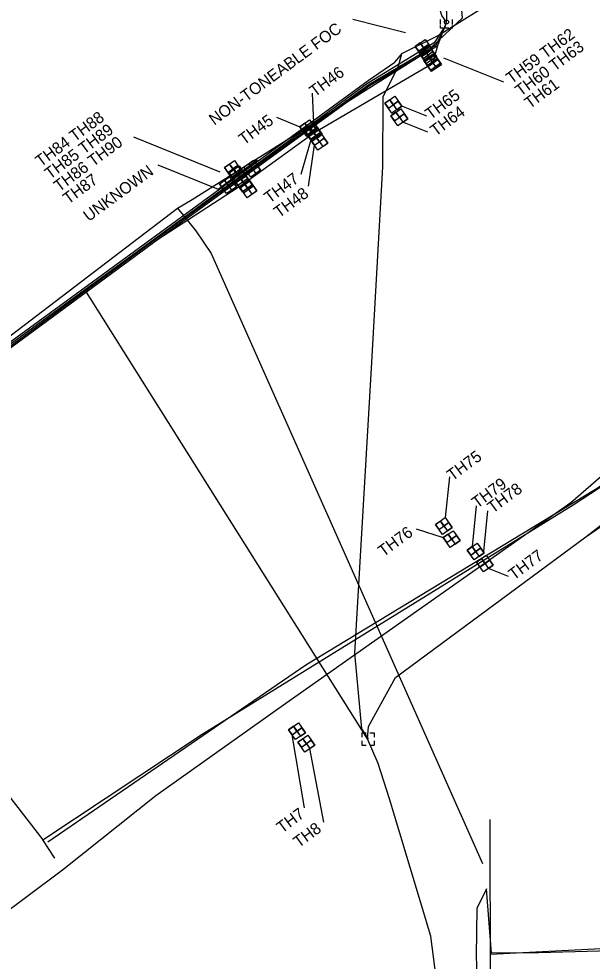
# Model space of a CAD drawing. Extents: x 507915 to 518914, y 880723 to 883087.
# Drawn here: x 509058.8 to 509177.3, y 882135.7 to 882330.6 of the extents above; entities that cross this region are included whole.
import ezdxf

# ---------------------------------------------------------------- set-up
doc = ezdxf.new("R2010")
doc.units = 0
for name, color, linetype in [('CGBack_ep', 7, 'Continuous'), ('CGFace_ep', 7, 'Continuous'), ('ConduitOT', 7, 'Continuous'), ('ConstLines', 7, 'Continuous'), ('Driveway_ep', 7, 'Continuous'), ('GuardrailLt_ep', 7, 'Continuous'), ('GuardrailRt_ep', 7, 'Continuous'), ('Miscellaneous2', 7, 'Continuous'), ('Miscellaneous3', 7, 'Continuous'), ('Miscellaneous4', 7, 'Continuous'), ('PavtAsphalt_ep', 7, 'Continuous'), ('PMBikeLane_ep', 7, 'Continuous'), ('PoleLight_ep', 7, 'Continuous')]:
    doc.layers.add(name, color=color, linetype=linetype)

msp = doc.modelspace()

# ---------------------------------------------------------------- linework, layer by layer
at = {"layer": 'CGBack_ep'}
msp.add_line((509100, 882295.41), (509108.02, 882301.47), dxfattribs=at)
at = {"layer": 'CGFace_ep'}
msp.add_line((509130.88, 882181.71), (509072.38, 882274.63), dxfattribs=at)
at = {"layer": 'ConduitOT'}
for p, q in [((509156.37, 882022.97), (509156.27, 882165.04)), ((509156.29, 882137.16), (509205.32, 882139.66))]:
    msp.add_line(p, q, dxfattribs=at)
at = {"layer": 'ConstLines'}
for points in [[(509091.54, 882291.51), (509094.58, 882293.28), (509143.11, 882323.78), (509150.52, 882330.83), (509150.2, 882334.84), (509149.51, 882377.66), (509149.68, 882420.56), (509148.41, 882517.05)], [(508881.68, 882117.95), (508987.36, 882213.45), (509037.07, 882249.99), (509091.54, 882291.51), (509095.39, 882286.81), (509098.53, 882282.11), (509154.64, 882155.93)], [(509199.56, 882066.8), (509200.82, 882115.11), (509201.3, 882138.4), (509166.31, 882137.42), (509156.53, 882137.36), (509155.46, 882150.65), (509153.51, 882146.59), (509153.35, 882136.84), (509153.6, 882128.58), (509150.89, 882127.59), (509149.73, 882127.8), (509148.69, 882127.65), (509147.06, 882127.81)]]:
    msp.add_lwpolyline(points, dxfattribs=at)
at = {"layer": 'Driveway_ep'}
msp.add_lwpolyline([(509470.15, 882412.29), (509450.24, 882402.26), (509403.86, 882379.8), (509373.73, 882360.54), (509360.26, 882353.19), (509318.09, 882328.86), (509274.11, 882302.04), (509240.02, 882280.9), (509217.6, 882265.28), (509213.42, 882264.48), (509212.3, 882264.04), (509210.28, 882262.92), (509172.92, 882230.49), (509113.97, 882188.99), (509087.11, 882169.95), (509067.76, 882154.57), (509006.28, 882108.6)], dxfattribs=at)
at = {"layer": 'GuardrailRt_ep'}
for p, q in [((509127.86, 882330.55), (509138.7, 882327.79)), ((509159.07, 882317.52), (509146.69, 882322.53)), ((509119.44, 882315.24), (509119.68, 882309.15)), ((509143.12, 882310.48), (509137.95, 882312.57)), ((509112.03, 882310.27), (509116.86, 882308.32)), ((509143.36, 882307.17), (509138.19, 882309.26)), ((509082.49, 882306.2), (509100.36, 882298.97)), ((509117.14, 882298.53), (509119.23, 882305.66)), ((509118.67, 882296.04), (509119.9, 882304.51)), ((509087.53, 882300.46), (509100, 882295.41)), ((509147.82, 882235.9), (509146.97, 882227.47)), ((509153.36, 882229.9), (509152.52, 882221.48)), ((509155.7, 882228.87), (509154.85, 882220.44)), ((509140.91, 882225.15), (509146.54, 882223.32)), ((509160.04, 882215.32), (509155.87, 882216.94)), ((509117.83, 882167.41), (509115.26, 882182.56)), ((509121.85, 882164.48), (509118.95, 882179.68))]:
    msp.add_line(p, q, dxfattribs=at)
at = {"layer": 'Miscellaneous2'}
for p, q in [((509145.96, 882329.48), (509145.96, 882330.48)), ((509147.21, 882329.98), (509147.21, 882329.98)), ((509148.46, 882329.48), (509148.46, 882330.48)), ((509145.96, 882328.73), (509145.96, 882329.23)), ((509146.46, 882328.73), (509145.96, 882328.73)), ((509147.71, 882328.73), (509146.71, 882328.73)), ((509148.46, 882328.73), (509147.96, 882328.73)), ((509148.46, 882328.73), (509148.46, 882329.23))]:
    msp.add_line(p, q, dxfattribs=at)
msp.add_circle((509147.21, 882329.98), 0.438, dxfattribs=at)
at = {"layer": 'Miscellaneous3'}
for points in [[(508882.11, 882139.28), (508990.02, 882214.29), (509029.72, 882243.96), (509087.02, 882285.78), (509130.99, 882317.86), (509136.55, 882321.71), (509138.14, 882323.57), (509145.35, 882327.1), (509198.61, 882360.32), (509243.19, 882384.95), (509308.25, 882420.73), (509348.67, 882443.03), (509435.21, 882484.91)], [(509130.88, 882181.71), (509131.05, 882184.29), (509136.67, 882194.39), (509176.07, 882223.49), (509242.19, 882269.15), (509301.71, 882304.81), (509379.73, 882350.73), (509420.13, 882372.96), (509456.8, 882391.95), (509476.67, 882399.78)], [(509130.88, 882181.71), (509131.05, 882184.29), (509136.67, 882194.39), (509176.07, 882223.49), (509204.83, 882245.76), (509242.19, 882269.15), (509301.71, 882304.81), (509379.73, 882350.73), (509420.13, 882372.96), (509456.8, 882391.95), (509476.67, 882399.78)], [(509137.94, 882323.42), (509137.22, 882320.77), (509134.02, 882314.51), (509133.96, 882300.01), (509131.64, 882258.39), (509128.15, 882199.4), (509129.61, 882183.81), (509130.98, 882181.68)], [(509152.04, 882062.9), (509150.55, 882090.16), (509143.99, 882140.92), (509135.39, 882169.31), (509133.07, 882176.58), (509130.88, 882181.71)]]:
    msp.add_lwpolyline(points, dxfattribs=at)
at = {"layer": 'Miscellaneous4'}
for p, q in [((509129.73, 882182.93), (509129.73, 882182.06)), ((509129.73, 882182.93), (509130.61, 882182.93)), ((509130.98, 882181.68), (509130.98, 882181.68)), ((509131.36, 882182.93), (509132.23, 882182.93)), ((509132.23, 882182.93), (509132.23, 882182.06)), ((509129.73, 882181.31), (509129.73, 882180.43)), ((509129.73, 882180.43), (509130.61, 882180.43)), ((509131.36, 882180.43), (509132.23, 882180.43)), ((509132.23, 882181.31), (509132.23, 882180.43))]:
    msp.add_line(p, q, dxfattribs=at)
at = {"layer": 'PavtAsphalt_ep'}
for points in [[(508946.27, 882182.61), (508990.71, 882213.97), (509030.15, 882243.24), (509087.3, 882285.27), (509131.16, 882317.05), (509145.15, 882325.32), (509146.91, 882329.08), (509147.21, 882329.98), (509147.25, 882330.89), (509146.76, 882351.04), (509146.84, 882378.71), (509146.15, 882394.1), (509143.64, 882423.51), (509144.5, 882493.5)], [(508946.38, 882183.08), (508990.55, 882214.25), (509029.91, 882243.66), (509087.28, 882285.5), (509130.89, 882317.31), (509144.84, 882325.87), (509146.91, 882329.08), (509147.21, 882329.98), (509146.27, 882331.32), (509140.54, 882349.76), (509141.42, 882378.79), (509141.44, 882421.55), (509136.29, 882492.59)], [(508884.81, 882150), (508991.11, 882213.84), (509030.43, 882243.07), (509087.63, 882285.11), (509131.44, 882316.89), (509145.44, 882325.15), (509147.21, 882329.98)], [(508946.67, 882182.29), (508991.11, 882213.84), (509030.43, 882243.07), (509087.63, 882285.11), (509105.29, 882296.6), (509119.78, 882307.05), (509144.41, 882321.5), (509145.44, 882325.15), (509147.21, 882329.98)], [(509064.73, 882160.38), (509118.15, 882196.99), (509178.01, 882233.34), (509198.91, 882246.9), (509212.24, 882254.11), (509211.47, 882255.05), (509211.94, 882257.47), (509212.92, 882261.94), (509216.93, 882269.31), (509226.27, 882274.92), (509234.36, 882278.84), (509241.09, 882279.12), (509244.59, 882279.94)]]:
    msp.add_lwpolyline(points, dxfattribs=at)
at = {"layer": 'PMBikeLane_ep'}
for p, q in [((509140.74, 882324.94), (509142.78, 882326.38)), ((509142.78, 882326.38), (509144.22, 882324.34)), ((509141.76, 882325.66), (509140.74, 882324.94)), ((509142.18, 882322.9), (509140.74, 882324.94)), ((509140.74, 882324.94), (509141.46, 882323.92)), ((509141.4, 882323.85), (509143.44, 882325.29)), ((509142.42, 882324.57), (509141.4, 882323.85)), ((509142.84, 882321.8), (509141.4, 882323.85)), ((509141.4, 882323.85), (509142.12, 882322.82)), ((509141.46, 882323.92), (509143.5, 882325.36)), ((509141.46, 882323.92), (509142.48, 882324.64)), ((509141.65, 882323.45), (509143.69, 882324.89)), ((509142.67, 882324.17), (509141.65, 882323.45)), ((509141.76, 882325.66), (509143.2, 882323.62)), ((509142.48, 882324.64), (509141.76, 882325.66)), ((509142.12, 882322.82), (509144.16, 882324.27)), ((509144.22, 882324.34), (509142.18, 882322.9)), ((509142.37, 882322.43), (509144.41, 882323.87)), ((509142.42, 882324.57), (509143.86, 882322.52)), ((509143.14, 882323.55), (509142.42, 882324.57)), ((509143.5, 882325.36), (509142.48, 882324.64)), ((509142.48, 882324.64), (509143.2, 882323.62)), ((509142.48, 882324.64), (509142.48, 882324.64)), ((509142.67, 882324.17), (509144.11, 882322.13)), ((509143.39, 882323.15), (509142.67, 882324.17)), ((509144.16, 882324.27), (509143.14, 882323.55)), ((509143.2, 882323.62), (509144.22, 882324.34)), ((509144.41, 882323.87), (509143.39, 882323.15)), ((509143.44, 882325.29), (509144.88, 882323.25)), ((509144.22, 882324.34), (509143.5, 882325.36)), ((509143.69, 882324.89), (509145.13, 882322.85)), ((509144.88, 882323.25), (509144.16, 882324.27)), ((509145.13, 882322.85), (509144.41, 882323.87)), ((509143.09, 882321.41), (509141.65, 882323.45)), ((509141.65, 882323.45), (509142.37, 882322.43)), ((509142.12, 882322.82), (509143.14, 882323.55)), ((509142.37, 882322.43), (509143.39, 882323.15)), ((509142.51, 882322.04), (509144.55, 882323.48)), ((509143.53, 882322.76), (509142.51, 882322.04)), ((509143.95, 882319.99), (509142.51, 882322.04)), ((509142.51, 882322.04), (509143.23, 882321.01)), ((509142.67, 882321.8), (509144.71, 882323.24)), ((509143.69, 882322.52), (509142.67, 882321.8)), ((509144.88, 882323.25), (509142.84, 882321.8)), ((509145.13, 882322.85), (509143.09, 882321.41)), ((509143.14, 882323.55), (509143.86, 882322.52)), ((509143.14, 882323.55), (509143.14, 882323.55)), ((509143.23, 882321.01), (509145.27, 882322.46)), ((509143.39, 882323.15), (509144.11, 882322.13)), ((509143.39, 882323.15), (509143.39, 882323.15)), ((509143.39, 882320.78), (509145.43, 882322.22)), ((509143.53, 882322.76), (509144.97, 882320.71)), ((509144.25, 882321.74), (509143.53, 882322.76)), ((509143.69, 882322.52), (509145.13, 882320.48)), ((509144.41, 882321.5), (509143.69, 882322.52)), ((509143.86, 882322.52), (509144.88, 882323.25)), ((509144.11, 882322.13), (509145.13, 882322.85)), ((509145.27, 882322.46), (509144.25, 882321.74)), ((509145.43, 882322.22), (509144.41, 882321.5)), ((509144.55, 882323.48), (509145.99, 882321.44)), ((509144.71, 882323.24), (509146.15, 882321.2)), ((509145.99, 882321.44), (509145.27, 882322.46)), ((509146.15, 882321.2), (509145.43, 882322.22)), ((509144.11, 882319.76), (509142.67, 882321.8)), ((509142.67, 882321.8), (509143.39, 882320.78)), ((509143.23, 882321.01), (509144.25, 882321.74)), ((509143.39, 882320.78), (509144.41, 882321.5)), ((509145.99, 882321.44), (509143.95, 882319.99)), ((509146.15, 882321.2), (509144.11, 882319.76)), ((509144.25, 882321.74), (509144.97, 882320.71)), ((509144.25, 882321.74), (509144.25, 882321.74)), ((509144.41, 882321.5), (509145.13, 882320.48)), ((509144.41, 882321.5), (509144.41, 882321.5)), ((509144.97, 882320.71), (509145.99, 882321.44)), ((509145.13, 882320.48), (509146.15, 882321.2)), ((509134.47, 882313.17), (509136.51, 882314.61)), ((509136.51, 882314.61), (509137.95, 882312.57)), ((509135.49, 882313.89), (509134.47, 882313.17)), ((509135.91, 882311.13), (509134.47, 882313.17)), ((509134.47, 882313.17), (509135.19, 882312.15)), ((509135.19, 882312.15), (509137.23, 882313.59)), ((509135.19, 882312.15), (509136.21, 882312.87)), ((509135.49, 882313.89), (509136.93, 882311.85)), ((509136.21, 882312.87), (509135.49, 882313.89)), ((509137.95, 882312.57), (509135.91, 882311.13)), ((509137.23, 882313.59), (509136.21, 882312.87)), ((509136.21, 882312.87), (509136.93, 882311.85)), ((509136.21, 882312.87), (509136.21, 882312.87)), ((509136.93, 882311.85), (509137.95, 882312.57)), ((509137.95, 882312.57), (509137.23, 882313.59)), ((509135.72, 882310.58), (509137.77, 882312.03)), ((509136.74, 882311.31), (509135.72, 882310.58)), ((509137.17, 882308.54), (509135.72, 882310.58)), ((509135.72, 882310.58), (509136.44, 882309.56)), ((509136.44, 882309.56), (509138.49, 882311.01)), ((509136.44, 882309.56), (509137.47, 882310.28)), ((509136.74, 882311.31), (509138.19, 882309.26)), ((509137.47, 882310.28), (509136.74, 882311.31)), ((509138.49, 882311.01), (509137.47, 882310.28)), ((509137.47, 882310.28), (509138.19, 882309.26)), ((509137.47, 882310.28), (509137.47, 882310.28)), ((509137.77, 882312.03), (509139.21, 882309.98)), ((509139.21, 882309.98), (509138.49, 882311.01)), ((509116.86, 882308.32), (509118.9, 882309.76)), ((509117.88, 882309.04), (509116.86, 882308.32)), ((509118.3, 882306.28), (509116.86, 882308.32)), ((509116.86, 882308.32), (509117.58, 882307.3)), ((509117.58, 882307.3), (509119.62, 882308.74)), ((509117.67, 882307.73), (509119.71, 882309.18)), ((509118.69, 882308.45), (509117.67, 882307.73)), ((509117.88, 882309.04), (509119.32, 882307)), ((509118.6, 882308.02), (509117.88, 882309.04)), ((509118.03, 882307.35), (509120.08, 882308.79)), ((509119.62, 882308.74), (509118.6, 882308.02)), ((509118.69, 882308.45), (509120.14, 882306.41)), ((509119.41, 882307.43), (509118.69, 882308.45)), ((509118.9, 882309.76), (509120.35, 882307.72)), ((509120.35, 882307.72), (509119.62, 882308.74)), ((509119.71, 882309.18), (509121.16, 882307.13)), ((509120.08, 882308.79), (509121.52, 882306.75)), ((509139.21, 882309.98), (509137.17, 882308.54)), ((509138.19, 882309.26), (509139.21, 882309.98)), ((509117.58, 882307.3), (509118.6, 882308.02)), ((509119.11, 882305.69), (509117.67, 882307.73)), ((509117.67, 882307.73), (509118.39, 882306.71)), ((509119.05, 882308.07), (509118.03, 882307.35)), ((509119.48, 882305.31), (509118.03, 882307.35)), ((509118.03, 882307.35), (509118.75, 882306.33)), ((509120.35, 882307.72), (509118.3, 882306.28)), ((509118.39, 882306.71), (509120.44, 882308.15)), ((509118.39, 882306.71), (509119.41, 882307.43)), ((509118.6, 882308.02), (509119.32, 882307)), ((509118.6, 882308.02), (509118.6, 882308.02)), ((509118.75, 882306.33), (509120.8, 882307.77)), ((509118.75, 882306.33), (509119.78, 882307.05)), ((509119.05, 882308.07), (509120.5, 882306.03)), ((509119.78, 882307.05), (509119.05, 882308.07)), ((509121.16, 882307.13), (509119.11, 882305.69)), ((509119.18, 882305.53), (509121.22, 882306.97)), ((509120.2, 882306.25), (509119.18, 882305.53)), ((509119.32, 882307), (509120.35, 882307.72)), ((509120.44, 882308.15), (509119.41, 882307.43)), ((509119.41, 882307.43), (509120.14, 882306.41)), ((509119.41, 882307.43), (509119.41, 882307.43)), ((509121.52, 882306.75), (509119.48, 882305.31)), ((509120.8, 882307.77), (509119.78, 882307.05)), ((509119.78, 882307.05), (509120.5, 882306.03)), ((509119.78, 882307.05), (509119.78, 882307.05)), ((509120.14, 882306.41), (509121.16, 882307.13)), ((509120.2, 882306.25), (509121.64, 882304.21)), ((509120.92, 882305.23), (509120.2, 882306.25)), ((509121.16, 882307.13), (509120.44, 882308.15)), ((509120.5, 882306.03), (509121.52, 882306.75)), ((509121.52, 882306.75), (509120.8, 882307.77)), ((509121.22, 882306.97), (509122.66, 882304.93)), ((509120.62, 882303.48), (509119.18, 882305.53)), ((509119.18, 882305.53), (509119.9, 882304.51)), ((509119.9, 882304.51), (509121.94, 882305.95)), ((509119.9, 882304.51), (509120.92, 882305.23)), ((509122.66, 882304.93), (509120.62, 882303.48)), ((509121.94, 882305.95), (509120.92, 882305.23)), ((509120.92, 882305.23), (509121.64, 882304.21)), ((509120.92, 882305.23), (509120.92, 882305.23)), ((509121.64, 882304.21), (509122.66, 882304.93)), ((509122.66, 882304.93), (509121.94, 882305.95)), ((509101.29, 882299.88), (509103.33, 882301.32)), ((509102.31, 882300.6), (509101.29, 882299.88)), ((509102.31, 882300.6), (509103.75, 882298.56)), ((509103.03, 882299.58), (509102.31, 882300.6)), ((509103.33, 882301.32), (509104.77, 882299.28)), ((509105.28, 882299.95), (509107.32, 882301.39)), ((509106.3, 882300.67), (509105.28, 882299.95)), ((509106.3, 882300.67), (509107.74, 882298.63)), ((509107.02, 882299.65), (509106.3, 882300.67)), ((509107.32, 882301.39), (509108.77, 882299.35)), ((509102.73, 882297.84), (509101.29, 882299.88)), ((509101.29, 882299.88), (509102.01, 882298.86)), ((509102.01, 882298.86), (509104.05, 882300.3)), ((509102.01, 882298.86), (509103.03, 882299.58)), ((509102.29, 882298.76), (509104.33, 882300.2)), ((509103.31, 882299.48), (509102.29, 882298.76)), ((509103.73, 882296.71), (509102.29, 882298.76)), ((509102.29, 882298.76), (509103.01, 882297.73)), ((509102.62, 882298.23), (509104.67, 882299.67)), ((509103.64, 882298.95), (509102.62, 882298.23)), ((509104.77, 882299.28), (509102.73, 882297.84)), ((509103.01, 882297.73), (509105.05, 882299.18)), ((509103.01, 882297.73), (509104.03, 882298.46)), ((509104.05, 882300.3), (509103.03, 882299.58)), ((509103.03, 882299.58), (509103.75, 882298.56)), ((509103.03, 882299.58), (509103.03, 882299.58)), ((509103.31, 882299.48), (509104.75, 882297.43)), ((509104.03, 882298.46), (509103.31, 882299.48)), ((509103.34, 882297.21), (509105.39, 882298.65)), ((509103.64, 882298.95), (509105.09, 882296.91)), ((509104.37, 882297.93), (509103.64, 882298.95)), ((509103.75, 882298.56), (509104.77, 882299.28)), ((509105.05, 882299.18), (509104.03, 882298.46)), ((509104.03, 882298.46), (509104.75, 882297.43)), ((509104.03, 882298.46), (509104.03, 882298.46)), ((509104.77, 882299.28), (509104.05, 882300.3)), ((509104.33, 882300.2), (509105.78, 882298.16)), ((509105.39, 882298.65), (509104.37, 882297.93)), ((509104.67, 882299.67), (509106.11, 882297.63)), ((509105.78, 882298.16), (509105.05, 882299.18)), ((509106.72, 882297.91), (509105.28, 882299.95)), ((509105.28, 882299.95), (509106, 882298.93)), ((509106.11, 882297.63), (509105.39, 882298.65)), ((509106, 882298.93), (509108.04, 882300.37)), ((509106, 882298.93), (509107.02, 882299.65)), ((509108.77, 882299.35), (509106.72, 882297.91)), ((509108.04, 882300.37), (509107.02, 882299.65)), ((509107.02, 882299.65), (509107.74, 882298.63)), ((509107.02, 882299.65), (509107.02, 882299.65)), ((509107.74, 882298.63), (509108.77, 882299.35)), ((509108.77, 882299.35), (509108.04, 882300.37)), ((509100.29, 882296.52), (509102.33, 882297.97)), ((509101.31, 882297.25), (509100.29, 882296.52)), ((509101.73, 882294.48), (509100.29, 882296.52)), ((509100.29, 882296.52), (509101.01, 882295.5)), ((509101.01, 882295.5), (509103.05, 882296.95)), ((509101.31, 882297.25), (509102.75, 882295.2)), ((509102.03, 882296.22), (509101.31, 882297.25)), ((509103.05, 882296.95), (509102.03, 882296.22)), ((509102.33, 882297.97), (509103.77, 882295.92)), ((509104.07, 882296.19), (509102.62, 882298.23)), ((509102.62, 882298.23), (509103.34, 882297.21)), ((509103.77, 882295.92), (509103.05, 882296.95)), ((509103.34, 882297.21), (509104.37, 882297.93)), ((509103.55, 882296.9), (509105.59, 882298.34)), ((509104.57, 882297.62), (509103.55, 882296.9)), ((509104.99, 882294.86), (509103.55, 882296.9)), ((509103.55, 882296.9), (509104.27, 882295.88)), ((509105.78, 882298.16), (509103.73, 882296.71)), ((509106.11, 882297.63), (509104.07, 882296.19)), ((509104.27, 882295.88), (509106.31, 882297.32)), ((509104.27, 882295.88), (509105.29, 882296.6)), ((509104.37, 882297.93), (509105.09, 882296.91)), ((509104.37, 882297.93), (509104.37, 882297.93)), ((509104.52, 882295.68), (509106.56, 882297.12)), ((509104.57, 882297.62), (509106.01, 882295.58)), ((509105.29, 882296.6), (509104.57, 882297.62)), ((509104.75, 882297.43), (509105.78, 882298.16)), ((509105.09, 882296.91), (509106.11, 882297.63)), ((509106.31, 882297.32), (509105.29, 882296.6)), ((509105.29, 882296.6), (509106.01, 882295.58)), ((509105.29, 882296.6), (509105.29, 882296.6)), ((509105.59, 882298.34), (509107.03, 882296.3)), ((509107.03, 882296.3), (509106.31, 882297.32)), ((509106.56, 882297.12), (509108, 882295.08)), ((509101.01, 882295.5), (509102.03, 882296.22)), ((509103.77, 882295.92), (509101.73, 882294.48)), ((509102.03, 882296.22), (509102.75, 882295.2)), ((509102.03, 882296.22), (509102.03, 882296.22)), ((509102.75, 882295.2), (509103.77, 882295.92)), ((509105.54, 882296.4), (509104.52, 882295.68)), ((509105.96, 882293.63), (509104.52, 882295.68)), ((509104.52, 882295.68), (509105.24, 882294.66)), ((509107.03, 882296.3), (509104.99, 882294.86)), ((509105.24, 882294.66), (509107.28, 882296.1)), ((509105.24, 882294.66), (509106.26, 882295.38)), ((509105.54, 882296.4), (509106.98, 882294.36)), ((509106.26, 882295.38), (509105.54, 882296.4)), ((509108, 882295.08), (509105.96, 882293.63)), ((509106.01, 882295.58), (509107.03, 882296.3)), ((509107.28, 882296.1), (509106.26, 882295.38)), ((509106.26, 882295.38), (509106.98, 882294.36)), ((509106.26, 882295.38), (509106.26, 882295.38)), ((509106.98, 882294.36), (509108, 882295.08)), ((509108, 882295.08), (509107.28, 882296.1)), ((509144.93, 882226.03), (509146.97, 882227.47)), ((509145.95, 882226.75), (509144.93, 882226.03)), ((509145.65, 882225.01), (509147.69, 882226.45)), ((509145.95, 882226.75), (509147.39, 882224.71)), ((509146.67, 882225.73), (509145.95, 882226.75)), ((509147.69, 882226.45), (509146.67, 882225.73)), ((509146.97, 882227.47), (509148.41, 882225.43)), ((509148.41, 882225.43), (509147.69, 882226.45)), ((509146.37, 882223.99), (509144.93, 882226.03)), ((509144.93, 882226.03), (509145.65, 882225.01)), ((509145.65, 882225.01), (509146.67, 882225.73)), ((509148.41, 882225.43), (509146.37, 882223.99)), ((509146.54, 882223.32), (509148.58, 882224.76)), ((509146.67, 882225.73), (509147.39, 882224.71)), ((509146.67, 882225.73), (509146.67, 882225.73)), ((509147.39, 882224.71), (509148.41, 882225.43)), ((509148.58, 882224.76), (509150.02, 882222.72)), ((509147.56, 882224.04), (509146.54, 882223.32)), ((509147.98, 882221.28), (509146.54, 882223.32)), ((509146.54, 882223.32), (509147.26, 882222.3)), ((509147.26, 882222.3), (509149.3, 882223.74)), ((509147.26, 882222.3), (509148.28, 882223.02)), ((509147.56, 882224.04), (509149, 882222)), ((509148.28, 882223.02), (509147.56, 882224.04)), ((509150.02, 882222.72), (509147.98, 882221.28)), ((509149.3, 882223.74), (509148.28, 882223.02)), ((509148.28, 882223.02), (509149, 882222)), ((509148.28, 882223.02), (509148.28, 882223.02)), ((509149, 882222), (509150.02, 882222.72)), ((509150.02, 882222.72), (509149.3, 882223.74)), ((509151.5, 882220.75), (509153.54, 882222.2)), ((509152.52, 882221.48), (509151.5, 882220.75)), ((509152.94, 882218.71), (509151.5, 882220.75)), ((509151.5, 882220.75), (509152.22, 882219.73)), ((509152.22, 882219.73), (509154.26, 882221.18)), ((509152.52, 882221.48), (509153.96, 882219.43)), ((509153.24, 882220.45), (509152.52, 882221.48)), ((509154.26, 882221.18), (509153.24, 882220.45)), ((509153.54, 882222.2), (509154.98, 882220.15)), ((509154.98, 882220.15), (509154.26, 882221.18)), ((509152.22, 882219.73), (509153.24, 882220.45)), ((509154.98, 882220.15), (509152.94, 882218.71)), ((509153.24, 882220.45), (509153.96, 882219.43)), ((509153.24, 882220.45), (509153.24, 882220.45)), ((509153.41, 882218.26), (509155.45, 882219.7)), ((509154.43, 882218.98), (509153.41, 882218.26)), ((509153.96, 882219.43), (509154.98, 882220.15)), ((509154.13, 882217.24), (509156.17, 882218.68)), ((509154.43, 882218.98), (509155.87, 882216.94)), ((509155.15, 882217.96), (509154.43, 882218.98)), ((509156.17, 882218.68), (509155.15, 882217.96)), ((509155.45, 882219.7), (509156.89, 882217.66)), ((509156.89, 882217.66), (509156.17, 882218.68)), ((509154.85, 882216.22), (509153.41, 882218.26)), ((509153.41, 882218.26), (509154.13, 882217.24)), ((509154.13, 882217.24), (509155.15, 882217.96)), ((509156.89, 882217.66), (509154.85, 882216.22)), ((509155.15, 882217.96), (509155.87, 882216.94)), ((509155.15, 882217.96), (509155.15, 882217.96)), ((509155.87, 882216.94), (509156.89, 882217.66)), ((509114.54, 882183.58), (509116.58, 882185.02)), ((509115.56, 882184.3), (509114.54, 882183.58)), ((509115.98, 882181.54), (509114.54, 882183.58)), ((509114.54, 882183.58), (509115.26, 882182.56)), ((509115.26, 882182.56), (509117.31, 882184)), ((509115.56, 882184.3), (509117.01, 882182.26)), ((509116.28, 882183.28), (509115.56, 882184.3)), ((509117.31, 882184), (509116.28, 882183.28)), ((509116.58, 882185.02), (509118.03, 882182.98)), ((509118.03, 882182.98), (509117.31, 882184)), ((509115.26, 882182.56), (509116.28, 882183.28)), ((509118.03, 882182.98), (509115.98, 882181.54)), ((509116.28, 882183.28), (509117.01, 882182.26)), ((509116.28, 882183.28), (509116.28, 882183.28)), ((509116.49, 882181), (509118.53, 882182.45)), ((509117.51, 882181.73), (509116.49, 882181)), ((509117.01, 882182.26), (509118.03, 882182.98)), ((509117.51, 882181.73), (509118.95, 882179.68)), ((509118.23, 882180.7), (509117.51, 882181.73)), ((509118.53, 882182.45), (509119.97, 882180.4)), ((509117.93, 882178.96), (509116.49, 882181)), ((509116.49, 882181), (509117.21, 882179.98)), ((509117.21, 882179.98), (509119.25, 882181.43)), ((509117.21, 882179.98), (509118.23, 882180.7)), ((509119.97, 882180.4), (509117.93, 882178.96)), ((509119.25, 882181.43), (509118.23, 882180.7)), ((509118.23, 882180.7), (509118.95, 882179.68)), ((509118.23, 882180.7), (509118.23, 882180.7)), ((509118.95, 882179.68), (509119.97, 882180.4)), ((509119.97, 882180.4), (509119.25, 882181.43))]:
    msp.add_line(p, q, dxfattribs=at)
at = {"layer": 'PoleLight_ep'}
for points in [[(509066.19, 882157), (509063.7, 882160.81), (509096.65, 882182.65), (509173.39, 882230.11), (509240.49, 882273.93), (509264.92, 882290.87), (509276.3, 882299.74), (509283.12, 882303.89), (509320.52, 882322.39), (509376.96, 882358.25), (509415.58, 882380.91), (509454.19, 882398.17), (509477.23, 882409.32)], [(508877.56, 882122.85), (509003.2, 882217.37), (509014.59, 882225.9), (509016.26, 882223.77), (509020.98, 882217.13), (509038.21, 882193.72), (509063.7, 882160.81)]]:
    msp.add_lwpolyline(points, dxfattribs=at)

# ---------------------------------------------------------------- texts
at = {"layer": 'GuardrailLt_ep'}
for s, p in [('NON-TONEABLE FOC', (509099.19, 882308.53)), ('TH59 TH62', (509160.65, 882317.09)), ('TH60 TH63', (509162.55, 882314.51)), ('TH46', (509119.98, 882314.39)), ('TH61 ', (509164.45, 882311.93)), ('TH65', (509143.92, 882309.68)), ('TH64', (509144.97, 882306.24)), ('TH84 TH88', (509063.29, 882299.91)), ('TH45', (509105.33, 882304.45)), ('TH85 TH89', (509065.19, 882297.34)), ('TH86 TH90', (509067.1, 882294.76)), ('UNKNOWN', (509073.2, 882288.59)), ('TH87', (509069, 882292.18)), ('TH47', (509110.6, 882292.39)), ('TH48', (509112.6, 882289.37)), ('TH75', (509148.43, 882234.96)), ('TH79', (509153.56, 882229.29)), ('TH78', (509156.79, 882228.27)), ('TH76', (509134.17, 882219.25)), ('TH77', (509161.15, 882214.43)), ('TH7', (509113.19, 882162.08)), ('TH8', (509116.65, 882159.08))]:
    msp.add_text(s, height=2.4, rotation=36.4175, dxfattribs=at).set_placement(p)

doc.saveas('drawing.dxf')
